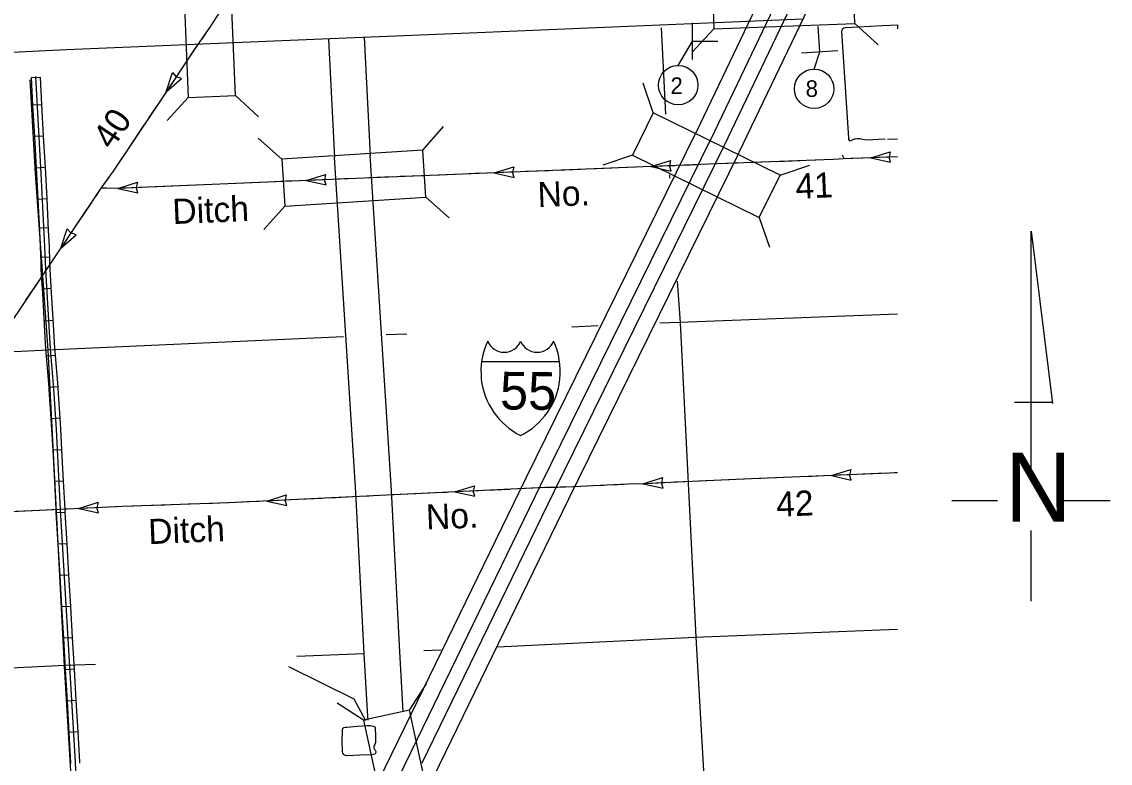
# Model space of a CAD drawing. Extents: x 9792 to 14027, y 9583 to 10649.
# Drawn here: x 10326 to 10878, y 10044 to 10420 of the extents above; entities that cross this region are included whole.
import ezdxf

# ---------------------------------------------------------------- set-up
doc = ezdxf.new("R2010")
doc.units = 0
for name, color, linetype in [('Default', 7, 'Continuous'), ('R_Border Notes', 7, 'Continuous'), ('R_Draft', 7, 'Continuous'), ('R_MOT', 7, 'Continuous')]:
    doc.layers.add(name, color=color, linetype=linetype)

msp = doc.modelspace()

# ---------------------------------------------------------------- linework, layer by layer
at = {"layer": 'Default'}
for p, q in [((10748.8, 10418.89), (10760.47, 10408.06)), ((10677.23, 10416.2), (10666.41, 10404.54)), ((10399.55, 10384.25), (10402.88, 10394.05)), ((10399.55, 10384.25), (10407.33, 10391.08)), ((10402.88, 10394.05), (10404.69, 10391.98)), ((10407.33, 10391.08), (10404.72, 10391.96)), ((10646.53, 10373.66), (10641.4, 10388.72)), ((10410.83, 10381.43), (10400.05, 10369.72)), ((10434.69, 10382.41), (10446.39, 10371.62)), ((10336.6, 10377.77), (10332.09, 10377.51)), ((10529.67, 10354.83), (10540.18, 10366.78)), ((10337.49, 10361.88), (10332.97, 10361.62)), ((10458.2, 10350.28), (10446.25, 10360.79)), ((10635.99, 10352.24), (10620.93, 10347.11)), ((10756.79, 10350.9), (10766.66, 10353.99)), ((10766.66, 10353.99), (10766.06, 10351.3)), ((10565.96, 10343.25), (10575.84, 10346.33)), ((10575.84, 10346.33), (10575.23, 10343.64)), ((10645.47, 10346.43), (10655.35, 10349.51)), ((10645.47, 10346.43), (10655.56, 10344.16)), ((10655.35, 10349.51), (10654.74, 10346.82)), ((10655.56, 10344.16), (10654.75, 10346.78)), ((10710.79, 10342.05), (10725.86, 10347.18)), ((10756.79, 10350.9), (10766.88, 10348.64)), ((10766.88, 10348.64), (10766.06, 10351.27)), ((10338.37, 10345.98), (10333.86, 10345.73)), ((10470.55, 10339.39), (10480.42, 10342.48)), ((10480.42, 10342.48), (10479.82, 10339.8)), ((10565.96, 10343.25), (10576.05, 10340.98)), ((10576.05, 10340.98), (10575.23, 10343.61)), ((10375.14, 10335.42), (10385.01, 10338.51)), ((10375.14, 10335.42), (10385.24, 10333.16)), ((10385.01, 10338.51), (10384.41, 10335.82)), ((10385.24, 10333.16), (10384.41, 10335.79)), ((10470.55, 10339.39), (10480.64, 10337.13)), ((10480.64, 10337.13), (10479.82, 10339.76)), ((10339.2, 10330.08), (10334.68, 10329.85)), ((10531.19, 10331.01), (10543.13, 10320.49)), ((10459.71, 10326.45), (10449.2, 10314.51)), ((10700.26, 10320.62), (10705.39, 10305.56)), ((10339.95, 10315.39), (10335.43, 10315.16)), ((10346.13, 10305.11), (10349.49, 10314.9)), ((10349.49, 10314.9), (10351.3, 10312.82)), ((10346.13, 10305.11), (10353.93, 10311.91)), ((10353.93, 10311.91), (10351.33, 10312.8)), ((10340.62, 10300.48), (10336.1, 10300.33)), ((10341.41, 10284.61), (10336.89, 10284.34)), ((10342.36, 10268.43), (10337.85, 10268.16)), ((10343.49, 10250.7), (10338.98, 10250.32)), ((10559.55, 10247.6), (10599.06, 10247.6)), ((10344.8, 10234.84), (10340.3, 10234.46)), ((10345.88, 10218.92), (10341.37, 10218.62)), ((10346.79, 10203), (10342.27, 10202.77)), ((10736.81, 10189.88), (10746.68, 10192.98)), ((10746.68, 10192.98), (10746.08, 10190.29)), ((10347.61, 10187.11), (10343.09, 10186.87)), ((10641.41, 10185.71), (10651.26, 10188.87)), ((10651.26, 10188.87), (10650.68, 10186.17)), ((10651.52, 10183.52), (10650.68, 10186.14)), ((10736.81, 10189.88), (10746.91, 10187.63)), ((10746.91, 10187.63), (10746.08, 10190.25)), ((10546.02, 10181.56), (10555.87, 10184.71)), ((10546.02, 10181.56), (10556.13, 10179.36)), ((10555.87, 10184.71), (10555.28, 10182.02)), ((10556.13, 10179.36), (10555.29, 10181.98)), ((10641.41, 10185.71), (10651.52, 10183.52)), ((10355.26, 10173.17), (10365.11, 10176.32)), ((10365.11, 10176.32), (10364.52, 10173.63)), ((10450.64, 10176.97), (10460.49, 10180.13)), ((10450.64, 10176.97), (10460.75, 10174.78)), ((10460.49, 10180.13), (10459.91, 10177.43)), ((10460.75, 10174.78), (10459.91, 10177.4)), ((10348.44, 10171.23), (10343.92, 10170.96)), ((10355.26, 10173.17), (10365.36, 10170.97)), ((10365.36, 10170.97), (10364.53, 10173.59)), ((10349.37, 10155.34), (10344.85, 10155.08)), ((10350.3, 10139.45), (10345.79, 10139.19)), ((10351.23, 10123.56), (10346.72, 10123.3)), ((10352.16, 10107.68), (10347.65, 10107.41)), ((10461.6, 10093.07), (10494.67, 10076.82)), ((10353.09, 10091.79), (10348.58, 10091.52)), ((10522.95, 10071.01), (10531.55, 10084.39)), ((10354.02, 10075.9), (10349.51, 10075.64)), ((10494.67, 10076.82), (10500.66, 10065.8)), ((10499.62, 10065.94), (10486.23, 10074.54)), ((10354.95, 10060.01), (10350.44, 10059.75))]:
    msp.add_line(p, q, dxfattribs=at)
for points in [[(10770.41, 10511.3), (10748.2, 10510.52), (10737.15, 10510.12), (10727.65, 10509.59), (10648.13, 10506.42), (10567.85, 10503.26), (10500.81, 10500.5), (10494.52, 10500.18), (10489.8, 10499.93), (10478.58, 10499.67), (10477.83, 10499.48), (10476.97, 10499.21), (10475.77, 10498.22), (10474.73, 10497.12), (10473.32, 10495.15), (10471.76, 10492.63), (10466.35, 10484.72), (10451.02, 10461.59), (10431.87, 10432.39), (10429.75, 10429.48), (10422.13, 10417.65), (10415.18, 10407.66), (10395.35, 10377.96), (10372.72, 10344.1)], [(10703.89, 10438.47), (10668.24, 10363.97)], [(10713.25, 10438.83), (10675.71, 10360.4)], [(10721.76, 10439.16), (10682.51, 10357.14)], [(10731.12, 10439.51), (10689.99, 10353.56)], [(10722.3, 10421.09), (10553.36, 10414.11), (10490.86, 10411.5)], [(10764.17, 10360.29), (10754.71, 10359.88), (10752.78, 10360.17), (10751.39, 10360.46), (10749.93, 10360.53), (10748.99, 10360.39), (10748.33, 10360.28), (10746.43, 10359.33), (10745.67, 10360.09), (10745.67, 10361.04), (10742.07, 10414.85), (10742.45, 10416.18), (10743.21, 10416.75), (10743.96, 10416.94), (10762.79, 10417.95)], [(10762.79, 10417.95), (10770.41, 10418.28)], [(10770.33, 10418.28), (10770.41, 10416.24)], [(10419.3, 10413.59), (10417.29, 10410.69)], [(10650.55, 10416.81), (10652.78, 10372.99)], [(10490.85, 10411.5), (10349.15, 10405.68), (10227.83, 10399.71), (10160.59, 10396.43)], [(10415.02, 10407.42), (10408.39, 10397.49)], [(10481.93, 10410.78), (10484.96, 10351.11)], [(10499.97, 10411.98), (10503.02, 10352.03)], [(10330.58, 10390.37), (10333.26, 10342.9)], [(10332.09, 10377.51), (10331.31, 10391.52), (10335.82, 10391.73)], [(10363.89, 9853.3), (10361.79, 9893.86), (10359.43, 9933.92), (10358.64, 9953.48), (10357.4, 9973.75), (10354.82, 10015.24), (10353.59, 10044.65), (10346.08, 10172.75), (10343.99, 10213.45), (10342.62, 10233.84), (10340.95, 10254.04), (10338.56, 10294.38), (10338.17, 10305.81), (10336.28, 10342.89), (10333.54, 10392.08)], [(10336.6, 10377.77), (10335.82, 10391.73)], [(10406.18, 10394.18), (10399.55, 10384.25)], [(10397.34, 10380.95), (10395.35, 10377.96), (10394.03, 10375.98)], [(10332.97, 10361.62), (10332.09, 10377.51)], [(10337.49, 10361.88), (10336.6, 10377.77)], [(10394.03, 10375.98), (10390.71, 10371.02)], [(10388.5, 10367.71), (10381.87, 10357.79)], [(10668.29, 10364.09), (10581.96, 10188.6), (10523.79, 10069.11)], [(10333.86, 10345.73), (10332.97, 10361.62)], [(10338.37, 10345.98), (10337.49, 10361.88)], [(10675.73, 10360.43), (10589.41, 10184.95), (10526.64, 10056.02)], [(10682.49, 10357.11), (10596.18, 10181.64), (10529.23, 10044.11)], [(10770.41, 10360.33), (10765.26, 10360.15)], [(10379.66, 10354.48), (10373.03, 10344.55)], [(10519.8, 10070.25), (10518.03, 10100.5), (10513.83, 10182.35), (10503.02, 10352.15)], [(10689.93, 10353.45), (10603.62, 10178), (10532.07, 10031.02)], [(10742.34, 10352.37), (10742.85, 10351.42), (10743.22, 10350.32)], [(10770.41, 10351.47), (10743.22, 10350.32), (10737.74, 10350.03), (10678.95, 10347.77), (10499.91, 10340.61), (10373.93, 10335.37), (10369.38, 10335.43), (10366.54, 10335.43)], [(10502.01, 10065.94), (10501.82, 10067.83), (10499.97, 10099.51), (10495.78, 10181.31), (10484.97, 10351)], [(10641.5, 10346.27), (10629.57, 10345.8)], [(10651.44, 10346.67), (10645.47, 10346.43)], [(10657.4, 10346.91), (10651.44, 10346.67)], [(10669.42, 10347.39), (10661.37, 10347.07)], [(10689.2, 10348.16), (10679.79, 10347.8)], [(10705.11, 10348.78), (10693.18, 10348.32)], [(10721.01, 10349.39), (10709.08, 10348.93)], [(10736.91, 10350), (10724.99, 10349.54)], [(10746.85, 10350.48), (10743.22, 10350.32), (10740.89, 10350.2)], [(10752.81, 10350.73), (10746.85, 10350.48)], [(10768.71, 10351.4), (10756.79, 10350.9)], [(10372.72, 10344.1), (10366.54, 10335.43), (10325.02, 10273.75), (10310.92, 10253.12), (10254.25, 10168.62), (10227.89, 10128.94), (10198.35, 10085.67), (10174.1, 10049.28), (10157.07, 10023.95), (10144.94, 10004.9), (10117.75, 9964.69), (10034.56, 9840.36), (10031.76, 9836.82), (10029.03, 9831.74), (9959.2, 9726.67), (9946.2, 9707.99), (9945.36, 9706.7)], [(10333.26, 10342.9), (10339.56, 10253.46), (10347.91, 10093.26), (10357.47, 9934.05), (10362.08, 9855.75)], [(10334.68, 10329.85), (10334.02, 10342.77), (10333.86, 10345.73)], [(10339.2, 10330.08), (10338.54, 10343.01), (10338.37, 10345.98)], [(10370.73, 10341.31), (10366.54, 10335.43), (10363.9, 10331.52)], [(10514.28, 10341.19), (10502.35, 10340.71)], [(10530.18, 10341.82), (10518.25, 10341.35)], [(10546.08, 10342.46), (10534.16, 10341.98)], [(10556.02, 10342.86), (10550.06, 10342.62)], [(10561.99, 10343.1), (10556.02, 10342.86)], [(10577.89, 10343.73), (10565.96, 10343.25)], [(10593.79, 10344.37), (10581.86, 10343.89)], [(10609.69, 10345), (10597.77, 10344.53)], [(10625.59, 10345.64), (10613.67, 10345.16)], [(10654.71, 10342.33), (10654.84, 10340.62)], [(10371.16, 10335.41), (10369.38, 10335.43), (10366.54, 10335.43)], [(10387.07, 10335.92), (10375.14, 10335.42)], [(10402.97, 10336.58), (10391.04, 10336.08)], [(10418.87, 10337.24), (10406.94, 10336.75)], [(10434.77, 10337.9), (10422.85, 10337.41)], [(10450.67, 10338.57), (10438.75, 10338.07)], [(10460.61, 10338.98), (10454.65, 10338.73)], [(10466.57, 10339.23), (10460.61, 10338.98)], [(10482.48, 10339.89), (10470.55, 10339.39)], [(10493.37, 10340.34), (10486.45, 10340.05)], [(10335.49, 10313.96), (10334.68, 10329.85)], [(10340.01, 10314.19), (10339.2, 10330.08)], [(10361.68, 10328.22), (10355.01, 10318.32)], [(10336.17, 10298.09), (10335.91, 10305.71), (10335.49, 10313.96)], [(10340.69, 10298.25), (10340.43, 10305.9), (10340.01, 10314.19)], [(10352.79, 10315.02), (10346.13, 10305.11)], [(10337.02, 10282.15), (10336.31, 10294.28), (10336.17, 10298.09)], [(10341.53, 10282.41), (10340.82, 10294.49), (10340.69, 10298.25)], [(10343.91, 10301.81), (10340.73, 10297.1)], [(10335.02, 10288.61), (10328.36, 10278.71)], [(10658.66, 10288.4), (10660.19, 10267.51), (10668.14, 10108.02), (10676.7, 9957.86)], [(10337.96, 10266.26), (10337.02, 10282.15)], [(10342.47, 10266.53), (10341.53, 10282.41)], [(10649.87, 10267.19), (10660, 10267.62), (10770.41, 10271.79)], [(10338.98, 10250.32), (10338.69, 10253.88), (10337.96, 10266.26)], [(10343.49, 10250.7), (10343.2, 10254.2), (10342.47, 10266.53)], [(10605.28, 10265.3), (10618.67, 10265.87)], [(10171.27, 10245.34), (10339.8, 10253.54), (10489.52, 10260.36)], [(10511.15, 10261.31), (10521.53, 10261.75)], [(10340.3, 10234.46), (10338.98, 10250.32)], [(10344.8, 10234.84), (10343.49, 10250.7)], [(10341.37, 10218.62), (10340.36, 10233.67), (10340.3, 10234.46)], [(10345.88, 10218.92), (10344.87, 10234.01), (10344.8, 10234.84)], [(10342.27, 10202.77), (10341.73, 10213.32), (10341.37, 10218.62)], [(10346.79, 10203), (10346.24, 10213.58), (10345.88, 10218.92)], [(10343.09, 10186.87), (10342.27, 10202.77)], [(10347.61, 10187.11), (10346.79, 10203)], [(10770.41, 10191.28), (10766.08, 10191.11), (10696.15, 10188.18), (10688.35, 10187.86), (10666.32, 10186.93), (10655.51, 10186.39), (10642.55, 10185.76), (10633.42, 10185.49), (10616.02, 10184.62), (10606.1, 10184.18), (10598.03, 10183.88), (10591.77, 10183.75), (10431.46, 10176.05), (10431.46, 10176.02), (10377.39, 10174.22), (10317.58, 10171.38), (10294.5, 10170.7), (10254.25, 10168.62)], [(10343.92, 10170.96), (10343.83, 10172.62), (10343.09, 10186.87)], [(10348.44, 10171.23), (10348.34, 10172.87), (10347.61, 10187.11)], [(10653.34, 10186.29), (10642.55, 10185.76), (10641.41, 10185.73)], [(10669.23, 10187.05), (10666.32, 10186.93), (10657.31, 10186.48)], [(10685.13, 10187.73), (10673.21, 10187.22)], [(10701.03, 10188.39), (10696.15, 10188.18), (10689.11, 10187.89)], [(10716.93, 10189.05), (10705.01, 10188.55)], [(10726.87, 10189.47), (10720.91, 10189.22)], [(10732.84, 10189.72), (10726.87, 10189.47)], [(10748.74, 10190.38), (10736.81, 10189.88)], [(10764.64, 10191.05), (10752.71, 10190.55)], [(10770.41, 10191.28), (10768.61, 10191.21)], [(10526.15, 10180.6), (10514.22, 10180.03)], [(10536.08, 10181.08), (10530.12, 10180.79)], [(10542.04, 10181.36), (10536.08, 10181.08)], [(10557.94, 10182.13), (10546.02, 10181.56)], [(10573.84, 10182.89), (10561.91, 10182.32)], [(10589.29, 10183.64), (10577.81, 10183.08)], [(10605.64, 10184.17), (10599.47, 10183.93)], [(10621.54, 10184.89), (10616.02, 10184.62), (10609.61, 10184.34)], [(10631.47, 10185.39), (10625.51, 10185.09)], [(10637.44, 10185.61), (10633.42, 10185.49), (10631.47, 10185.39)], [(10414.89, 10175.47), (10402.96, 10175.07)], [(10430.8, 10176), (10418.87, 10175.6)], [(10440.7, 10176.49), (10434.74, 10176.21)], [(10446.66, 10176.78), (10440.7, 10176.49)], [(10462.56, 10177.54), (10450.64, 10176.97)], [(10478.46, 10178.31), (10466.53, 10177.74)], [(10494.35, 10179.07), (10482.43, 10178.5)], [(10502.53, 10179.47), (10498.33, 10179.26)], [(10335.38, 10172.22), (10323.46, 10171.66)], [(10343.83, 10172.63), (10339.36, 10172.41)], [(10344.85, 10155.08), (10343.92, 10170.96)], [(10351.28, 10172.98), (10348.34, 10172.84)], [(10349.37, 10155.34), (10348.44, 10171.23)], [(10367.18, 10173.73), (10355.26, 10173.17)], [(10383.08, 10174.41), (10377.39, 10174.22), (10371.15, 10173.92)], [(10398.98, 10174.94), (10387.06, 10174.54)], [(10345.79, 10139.19), (10344.85, 10155.08)], [(10350.3, 10139.45), (10349.37, 10155.34)], [(10346.72, 10123.3), (10345.79, 10139.19)], [(10351.23, 10123.56), (10350.3, 10139.45)], [(10347.65, 10107.41), (10346.72, 10123.3)], [(10352.16, 10107.68), (10351.23, 10123.56)], [(10567.62, 10103.03), (10667.6, 10107.98), (10770.41, 10112.03)], [(10348.58, 10091.52), (10347.65, 10107.41)], [(10353.09, 10091.79), (10352.16, 10107.68)], [(10465.8, 10098.42), (10499.62, 10099.75)], [(10530.26, 10101.18), (10538.82, 10101.6)], [(10181.46, 10085.62), (10348.54, 10093.79), (10363.71, 10094.39)], [(10349.51, 10075.64), (10348.58, 10091.52)], [(10354.02, 10075.9), (10353.09, 10091.79)], [(10350.44, 10059.75), (10349.51, 10075.64)], [(10354.95, 10060.01), (10354.02, 10075.9)], [(10523.79, 10069.11), (10497.13, 10014.34), (10427.28, 9870.88), (10375.52, 9765.35)], [(10351.36, 10043.9), (10351.33, 10044.53), (10350.44, 10059.75)], [(10355.88, 10044.09), (10355.85, 10044.76), (10354.95, 10060.01)], [(10497.75, 10048.13), (10491.02, 10047.88), (10490.06, 10048.25), (10489.65, 10048.59), (10489.15, 10049.21), (10489.06, 10049.88), (10488.98, 10051.09), (10488.89, 10054.44), (10488.94, 10061.08), (10489.15, 10061.8), (10489.65, 10062.17), (10490.36, 10062.42), (10491.23, 10062.42), (10496.62, 10062.88)], [(10496.62, 10062.88), (10501.39, 10063.22), (10503.27, 10063.22), (10504.6, 10062.97), (10505.35, 10062.55), (10505.6, 10062.13), (10505.69, 10057.66), (10505.65, 10054.65), (10505.44, 10053.64), (10505.1, 10053.1), (10504.85, 10052.6), (10504.85, 10051.89), (10505.1, 10051.26), (10505.52, 10050.8), (10505.77, 10050.43), (10505.86, 10049.97), (10505.86, 10049.51), (10505.56, 10048.92), (10505.31, 10048.67), (10504.1, 10048.42), (10497.75, 10048.13)], [(10526.64, 10056.01), (10434.73, 9867.24), (10384.95, 9765.75)]]:
    msp.add_lwpolyline(points, dxfattribs=at)
for points in [[(10407.9, 10452.98), (10410.83, 10381.43), (10434.69, 10382.41), (10431.75, 10453.96)], [(10677.23, 10416.2), (10748.8, 10418.89), (10747.91, 10442.74), (10676.34, 10440.06)], [(10635.99, 10352.24), (10700.26, 10320.62), (10710.79, 10342.05), (10646.53, 10373.66)], [(10459.71, 10326.45), (10531.19, 10331.01), (10529.67, 10354.83), (10458.2, 10350.28)], [(10499.62, 10065.94), (10514.83, 9995.95), (10538.16, 10001.02), (10522.95, 10071.01)]]:
    msp.add_lwpolyline(points, close=True, dxfattribs=at)
for centre, radius, start, end in [((10596.27, 10242.46), 37.08, 155.2204, 185.7928), ((10570.97, 10261.4), 9.03, 202.1459, 337.3414), ((10587.64, 10261.4), 9.03, 202.6586, 337.8541), ((10562.34, 10242.46), 37.08, 354.2072, 24.7796), ((10595.58, 10242.77), 36.43, 186.3923, 243.4571), ((10563.02, 10242.77), 36.43, 296.5429, 353.6077)]:
    msp.add_arc(centre, radius, start, end, dxfattribs=at)
at = {"layer": 'R_Border Notes'}
for p, q in [((10659.2, 10397.7), (10666.44, 10409.94)), ((10728.08, 10395.86), (10730.97, 10404.58))]:
    msp.add_line(p, q, dxfattribs=at)
for centre in [(10659.2, 10387.73), (10728.08, 10385.89)]:
    msp.add_circle(centre, 9.97, dxfattribs=at)
at = {"layer": 'R_Draft'}
for p, q in [((10838.06, 10313.73), (10848.98, 10226.45)), ((10838.06, 10191.69), (10838.06, 10313.73)), ((10829.6, 10227.09), (10849, 10227.09)), ((10797.93, 10177.31), (10821.08, 10177.31)), ((10853.47, 10177.31), (10878.19, 10177.31)), ((10838.06, 10126.23), (10838.06, 10162.12))]:
    msp.add_line(p, q, dxfattribs=at)
at = {"layer": 'R_MOT'}
for p, q in [((10666.48, 10400.72), (10666.39, 10419.25)), ((10730.97, 10404.58), (10730.18, 10417.47)), ((10666.44, 10409.94), (10679.35, 10410)), ((10740.17, 10405.14), (10721.68, 10404))]:
    msp.add_line(p, q, dxfattribs=at)

# ---------------------------------------------------------------- texts
at = {"layer": 'Default'}
for s, height, rotation, p in [('40', 12.732, 56.251, (10372.18, 10354.48)), ('41', 12.732, 2.3947, (10718.9, 10330.13)), ('No.', 12.732, 2.2888, (10588.13, 10325.87)), ('Ditch', 12.732, 2.3831, (10403.03, 10317.29)), ('55', 19.098, 359.5284, (10568.82, 10223.38)), ('42', 12.732, 2.3947, (10709.12, 10168.94)), ('No.', 12.732, 2.2888, (10531.56, 10162.49)), ('Ditch', 12.732, 2.3831, (10390.79, 10155.08))]:
    msp.add_text(s, height=height, rotation=rotation, dxfattribs=at).set_placement(p)
at = {"layer": 'R_Border Notes'}
for s, p in [('2', (10655.28, 10383.24)), ('8', (10723.79, 10381.75))]:
    msp.add_text(s, height=8.4, dxfattribs=at).set_placement(p)
at = {"layer": 'R_Draft'}
msp.add_text('N', height=34.9, dxfattribs=at).set_placement((10824.83, 10166.56))

doc.saveas('drawing.dxf')
